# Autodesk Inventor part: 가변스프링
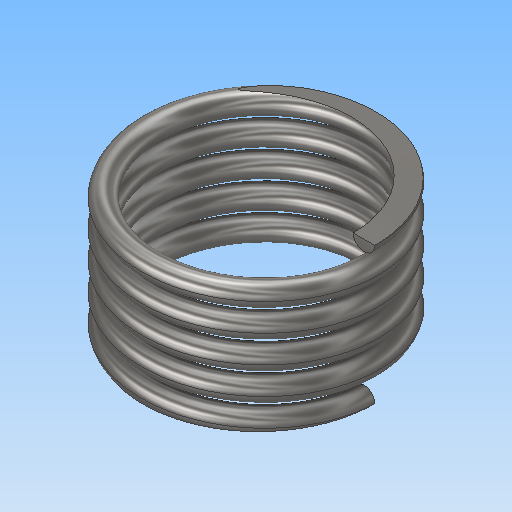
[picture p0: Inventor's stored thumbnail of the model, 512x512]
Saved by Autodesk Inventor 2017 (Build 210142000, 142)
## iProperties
Part Number: 가변스프링
Material: 스테인레스 스틸
Document SubType Name: Modeling
Designer: mrc
Density: 8 g/cm^3
Appearance: 반연마
Mass: 7.76831 g
Surface Area: 19.7146 cm^2
Volume: 0.971039 cm^3
Author: mrc
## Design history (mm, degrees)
sketch "스케치1"
  geometry: L1 (0, 0)-(10, 0); L2 (10, 0)-(10, 12.7); L3 (10, 12.7)-(0, 12.7); L4 (0, 12.7)-(0, 0); C1 r 1 at (10, 0)
  constraints: 8 end point, 2 parallel, 1 centre point, 1 coincident, 1 horizontal, 1 perpendicular
  dimensions: "d0" = 12.7 distance of L1.end L2.end (derived); "d1" = 20 diameter of L2 L4; "d2" = 2 diameter of C1
feature "코일1" sketch "스케치1" pitch "d3" = 10; turns "d5" = 5; dims "d4" = 12.7 (= d0), "d6" = 0, angle "d7" = 90 deg, angle "d8" = 90 deg, "d9" = 0, "d10" = 0
sketch "스케치2"
  geometry: L1 (-18.58, 0)-(18.58, 0); L2 (18.58, 0)-(18.58, 12.7); L3 (18.58, 12.7)-(-18.58, 12.7); L4 (-18.58, 12.7)-(-18.58, 0); 2 further points
  constraints: 8 end point, 2 parallel, 1 coincident, 1 horizontal, 1 midpoint, 1 perpendicular
  dimensions: "d11" = 12.7 distance of L1.end L2.end (= d0); "d12" = 37.15926 distance of L2.end L3.end
extrude "돌출1" sketch "스케치2" stored distance "d13" = 0; taper "d14" = 0 deg
node "솔리드1"
